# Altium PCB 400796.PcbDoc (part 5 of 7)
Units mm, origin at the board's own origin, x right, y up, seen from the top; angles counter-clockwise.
Board outline 53 x 53 mm, 6 copper layers (Top Layer, Mid Layer 1, Mid Layer 2, Mid Layer 3, Mid Layer 4, Bottom Layer), stack 1.494 mm thick; 319 components, 236 nets, 1249 pads, 2569 vias.
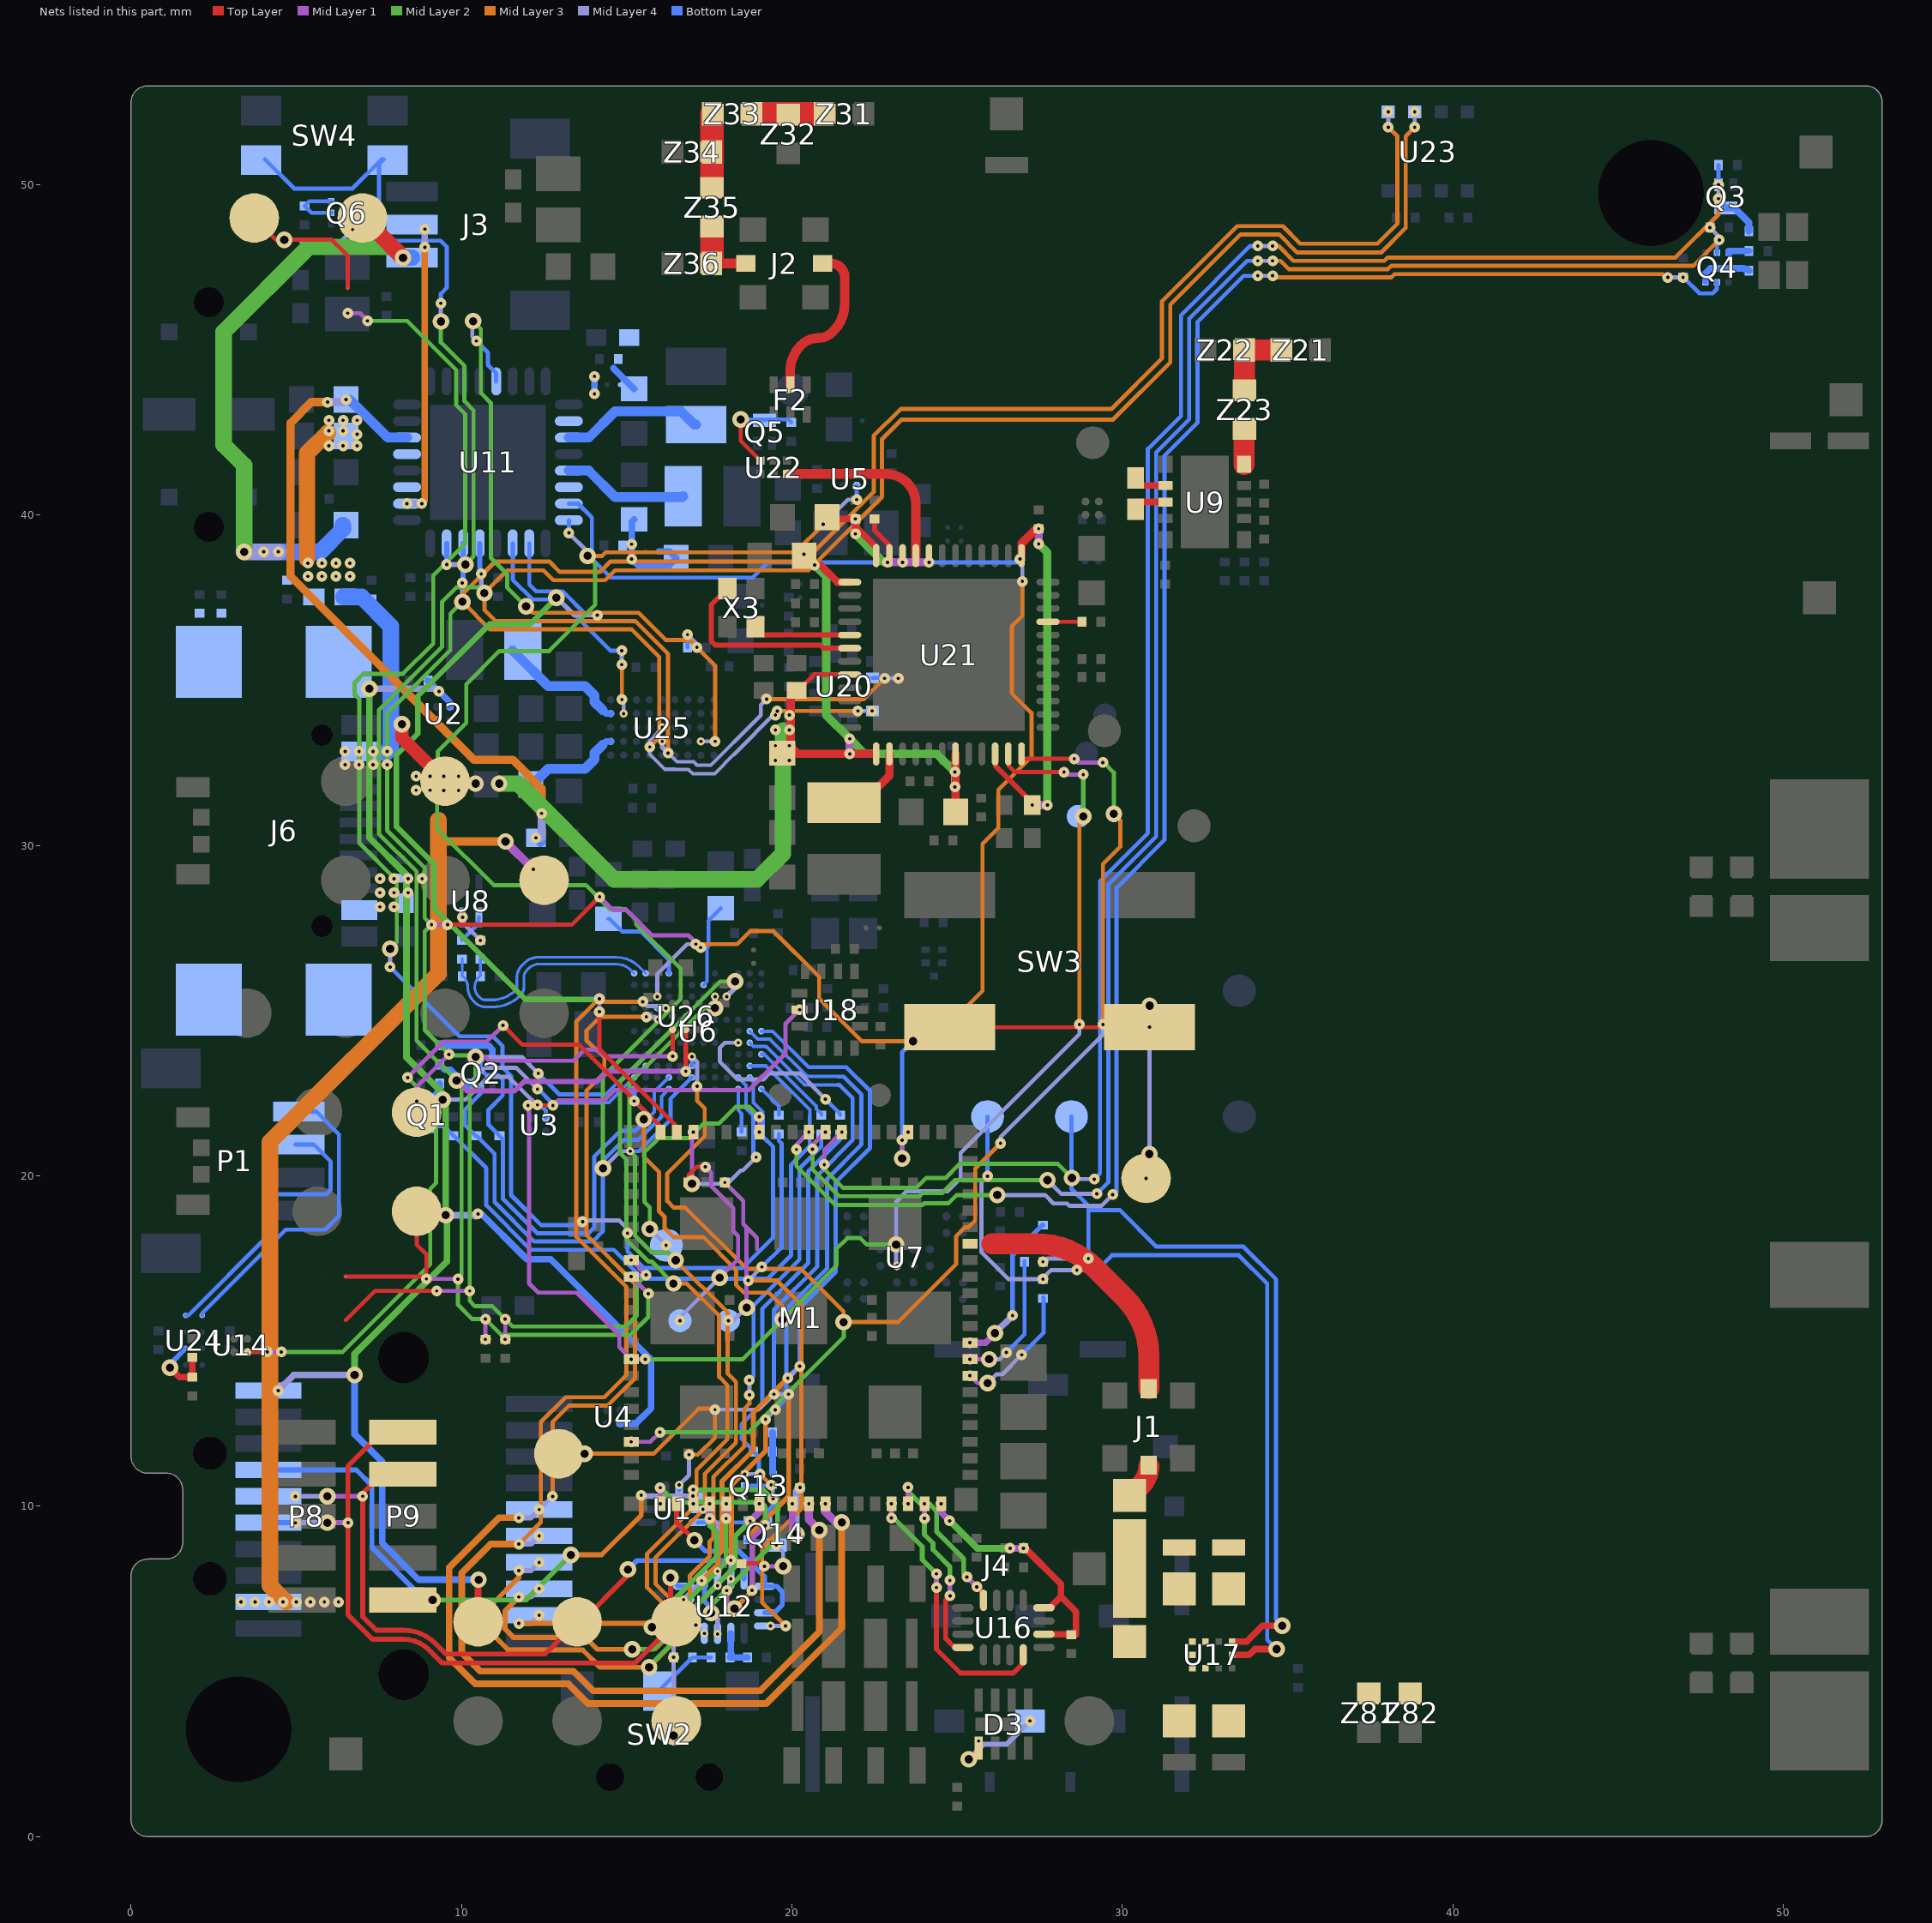
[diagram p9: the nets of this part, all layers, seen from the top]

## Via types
v1: diameter 0.325, hole 0.1, Mid Layer 4 to Bottom Layer, tented both sides, 675 vias
v2: diameter 0.325, hole 0.1, Top Layer to Mid Layer 1, tented both sides, 569 vias
v3: diameter 0.325, hole 0.1, Mid Layer 3 to Mid Layer 4, tented both sides, 384 vias
v4: diameter 0.5, hole 0.25, Mid Layer 1 to Mid Layer 4, tented both sides, 312 vias
v5: diameter 0.325, hole 0.1, Mid Layer 1 to Mid Layer 2, tented both sides, 265 vias
v6: diameter 0.5, hole 0.25, Top Layer to Bottom Layer, tented both sides, 175 vias
v7: diameter 0.25, hole 0.1, Mid Layer 4 to Bottom Layer, tented both sides, 105 vias
v8: diameter 0.325, hole 0.1, Top Layer to Mid Layer 1, tented top, 67 vias
v9: diameter 0.25, hole 0.1, Top Layer to Mid Layer 1, tented both sides, 17 vias

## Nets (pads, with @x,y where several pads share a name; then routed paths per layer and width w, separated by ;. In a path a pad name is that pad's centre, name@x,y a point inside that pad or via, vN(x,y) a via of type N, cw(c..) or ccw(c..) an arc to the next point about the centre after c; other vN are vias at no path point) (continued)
NetF2_6: F2.6 J2.1 | length 5
  Top Layer w0.29: F2.6@19.95,43.95 19.95,44.376 cw(c21.024,44.376) 20.265,45.136 20.275,45.146 cw(c20.8,44.622) 20.8,45.364 ccw(c20.8,45.959) 21.22,45.538 21.254,45.572 ccw(c20.421,46.406) 21.6,46.406 21.6,47.201 ccw(c21.173,47.201) 21.475,47.503 ccw(c21.183,47.211) 21.183,47.623 J2.1@20.928,47.623
NetJ1_1: J1.1 M1.35 | length 7.5
  Top Layer w0.638: 26.061,17.949 27.386,17.949 cw(c27.386,15.409) 29.182,17.205 30.056,16.331 cw(c28.26,14.535) 30.8,14.535 J1.1@30.8,13.56
NetJ1_3: J1.3 Z7.1 | length 1.1
  Top Layer w0.638: Z7.1@30.219,10.295 30.564,10.64 ccw(c29.994,11.21) J1.3@30.8,11.21
NetJ2_3: J2.3 Z35.1 Z36.1 | length 2.1
  Top Layer w0.29: Z36.1@17.582,47.623 J2.3@18.608,47.623
  Top Layer w0.71: Z36.1@17.582,47.623 Z35.1@17.581,48.719
NetL1_2: L1.2 U6.B6 | length 2.5
  Bottom Layer w0.105: U6.B6@17.325,25.78 17.432,25.887 17.432,26.907 17.475,26.95
  Bottom Layer w0.125: 17.475,26.95 17.475,27.73 L1.2@17.85,28.105
NetL2_2: L2.2 U6.A9 | length 2.8
  Bottom Layer w0.125: L2.2@14.45,27.78 14.475,27.78 14.854,27.401 15.423,27.401 16.275,26.549 U6.A9@16.275,26.13
NetL5_1: L5.1 U9.8 | length 1
  Top Layer w0.2: L5.1@30.4,40.25 30.55,40.4 30.667,40.4 U9.8@31.313,40.4
NetL5_2: L5.2 U9.7 | length 1
  Top Layer w0.2: L5.2@30.4,41.05 30.55,40.9 30.667,40.9 U9.7@31.313,40.9
NetL6_1: L6.1 U21.26 | length 2.4
  Top Layer w0.254: L6.1@21.575,31.297 22.063,31.785 22.621,31.785 22.95,32.113 U21.26@22.95,32.775
NetM1_2: M1.2 SB6.1 | length 6.6
  Mid Layer 1 w0.15: v2(16.013,10.075) v5(16.013,10.56) ; v2(18.793,7.452) 18.793,9.017 v5(19.192,9.415)
  Mid Layer 2 w0.15: v5(16.013,10.56) 16.452,10.121 19.064,10.121 19.192,9.993 v5(19.192,9.415)
NetM1_3: M1.3 U12.5 U12.7 | length 5.8
  Top Layer w0.15: M1.3@16.513,10.075 16.513,9.509 v6(17.051,8.97)
  Bottom Layer w0.15: v6(17.051,8.97) 17.381,8.64 18.397,8.64 19.175,7.863 U12.5@19.175,7.575 19.543,7.575 19.71,7.409 19.71,7.009 19.475,6.775 U12.7@19.175,6.775
NetM1_4: M1.4 U12.1 U12.11 | length 9.8
  Mid Layer 1 w0.15: v2(17.013,10.075) v5(17.013,10.498)
  Mid Layer 2 w0.15: v5(17.013,10.498) 19.127,10.498 19.564,10.06 19.564,9.008 17.555,6.998 v4(17.555,6.767)
  Mid Layer 4 w0.15: v4(17.555,6.767) 17.75,6.571 v7(17.75,6.132)
  Bottom Layer w0.15: U12.1@17.35,7.8 17.35,7.124 17.75,6.724 U12.11@17.75,6.15 v7(17.75,6.132)
NetM1_10: M1.10 R1.2 | length 2.7
  Mid Layer 1 w0.203: v2(20.017,10.075) 20.017,9.266 v4(20.133,9.15) ; v4@20.057,9.074 v4@20.133,8.998
  Mid Layer 4 w0.203: v4@20.133,8.998 v4(20.133,9.15) 20.133,10.456 v1(20.242,10.566)
NetM1_27: M1.27 R27.1 | length 4.2
  Mid Layer 1 w0.125: v2(25.388,13.95) 25.61,13.728 v4(25.925,13.728)
  Mid Layer 4 w0.125: v4@26.077,13.728 v4(25.925,13.728) 26.189,13.992 26.362,13.992 v1(26.953,14.583)
  Bottom Layer w0.125: v1(26.953,14.583) 27.615,15.245 27.615,16.315 R27.1@27.6,16.315
NetM1_28: M1.28 R28.1 | length 4.2
  Mid Layer 1 w0.125: v2(25.388,14.45) v4(25.969,14.45)
  Mid Layer 4 w0.125: v4(25.969,14.45) 26.289,14.45 v1(26.489,14.651)
  Bottom Layer w0.125: v1(26.489,14.651) 27.04,15.201 R28.1@27.04,17.425
NetM1_29: M1.29 R29.1 | length 4.8
  Mid Layer 1 w0.2: v2(25.388,14.95) 25.856,14.95 v4(26.146,15.24)
  Mid Layer 4 w0.2: v4(26.146,15.24) 26.675,15.769 v1(26.675,15.773)
  Bottom Layer w0.15: v1(26.675,15.773) 26.675,17.603 27.582,18.51 R29.1@27.6,18.51
NetM1_44: M1.44 SW3.2 TP36.1 U6.C10 U11.7 | length 59.7
  Top Layer w0.125: SW3.2@24.775,24.5 v2(30.825,24.5)
  Mid Layer 1 w0.125: v4(23.335,20.526) 23.335,21.147 v2(23.513,21.325) ; v2(30.719,19.925) 30.82,20.026 v4(30.82,20.662) ; v2(30.825,24.5) v4(30.825,25.153)
  Mid Layer 3 w0.125: v3(17.089,27.015) 18.343,27.015 18.735,27.407 19.442,27.407 20.823,26.027 20.823,25.369 22.117,24.075 v6(23.663,24.075) 23.913,24.075 24.282,24.444 24.616,24.444 25.767,25.595 25.767,30.047 26.25,30.53 26.25,31.688 27.251,32.689 27.251,34.014 26.657,34.608 26.657,36.638 26.975,36.957 v3(26.975,38)
  Mid Layer 4 w0.125: v7(15.925,25.43) 15.925,26.111 16.829,27.015 v3(17.089,27.015) ; v4(23.335,20.526) v1(23.335,21.08) ; v1(26.9,38.675) 26.975,38.6 v3(26.975,38) ; v4(30.82,20.662) 30.825,20.667 v4(30.825,25.153)
  Bottom Layer w0.125: U11.7@13.25,40.35 13.525,40.35 13.875,40 13.947,39.928 13.947,38.685 14.52,38.112 18.812,38.112 19.275,38.575 26.8,38.575 v1(26.9,38.675) ; v1@23.391,21.055 23.335,21.11 23.335,23.746 v6(23.663,24.075)
NetM1_48: M1.48 Q3.1 R44.2 | length 56.9
  Mid Layer 1 w0.125: v5(20.979,20.343) 20.979,20.791 v2(21.513,21.325)
  Mid Layer 2 w0.125: v5(20.979,20.343) 20.979,20.207 21.549,19.637 23.758,19.637 24.056,19.935 24.646,19.935 25.077,20.366 28.044,20.366 v4(28.475,19.935)
  Mid Layer 3 w0.125: v3(34.55,48.15) 34.73,48.15 35.18,47.7 37.932,47.7 38.032,47.8 46.744,47.8 48.044,49.099 v3(48.044,49.583)
  Mid Layer 4 w0.125: v4(28.475,19.935) 28.508,19.902 v1(29.15,19.902) ; v1(34.1,48.15) v3(34.55,48.15) ; v3(48.044,49.583) v1(48.044,50.004)
  Bottom Layer w0.125: v1(29.15,19.902) 29.325,20.077 29.325,28.925 30.775,30.375 30.775,42.007 31.775,43.007 31.775,46.057 33.868,48.15 v1(34.1,48.15) ; v1(48.044,50.004) R44.2@48.044,50.601
NetM1_49: M1.49 Q4.5 R46.2 | length 56.9
  Mid Layer 1 w0.125: v5(20.627,20.809) 20.627,20.939 v2(21.013,21.325)
  Mid Layer 2 w0.125: v5(20.627,20.809) 20.627,20.185 21.427,19.385 23.859,19.385 23.958,19.484 24.555,19.484 24.943,19.871 v4(27.734,19.871)
  Mid Layer 3 w0.125: v3(34.55,47.7) 34.788,47.7 35.038,47.45 38.036,47.45 38.136,47.55 47.283,47.55 v3(48.068,48.334)
  Mid Layer 4 w0.125: v4(27.734,19.871) 28.153,19.452 29.225,19.452 v1(29.23,19.457) ; v1(34.1,47.7) v3(34.55,47.7) ; v1(47.786,48.708) 48.068,48.427 v3(48.068,48.334)
  Bottom Layer w0.125: v1(29.23,19.457) 29.575,19.802 29.575,28.821 31.025,30.271 31.025,41.904 32.025,42.904 32.025,45.954 33.771,47.7 v1(34.1,47.7) ; v1(47.786,48.708) 48,48.495 Q4.5@48,47.925
NetM1_50: M1.50 Q4.2 R45.2 | length 56
  Mid Layer 1 w0.125: v5(20.135,20.8) 20.135,20.947 v2(20.513,21.325)
  Mid Layer 2 w0.125: v5(20.135,20.8) 20.135,20.295 21.312,19.118 23.946,19.118 24.001,19.173 24.743,19.173 24.99,19.42 v4(26.218,19.42)
  Mid Layer 3 w0.125: v3(34.551,47.249) 34.6,47.2 38.139,47.2 38.239,47.3 46.356,47.3 46.456,47.2 v3(46.51,47.2)
  Mid Layer 4 w0.125: v4(26.218,19.42) 27.663,19.42 27.917,19.166 28.329,19.166 28.405,19.091 29.368,19.091 v1(29.711,19.434) ; v1(34.101,47.249) v3(34.551,47.249) ; v3(46.51,47.2) v1(46.975,47.2)
  Bottom Layer w0.125: v1(29.711,19.434) 29.734,19.434 29.825,19.525 29.825,28.718 31.275,30.168 31.275,41.8 32.275,42.8 32.275,45.85 33.674,47.249 v1(34.101,47.249) ; R45.2@46.975,47.21 47.472,46.712 47.865,46.712 47.992,46.84 47.992,47.067 Q4.2@48,47.075
NetM1_53: M1.53 TP23.1 | length 7.6
  Mid Layer 1 w0.125: v2(19.013,21.325) v5(19.013,21.79)
  Mid Layer 2 w0.125: v4(15.7,18.39) 15.7,19.052 15.534,19.218 15.534,20.707 15.971,21.144 16.893,21.144 17.337,21.587 17.796,21.587 18.296,22.087 18.716,22.087 v5(19.013,21.79)
  Mid Layer 4 w0.125: v4@15.777,18.314 v1(16.19,17.9)
  Bottom Layer w0.125: v1(16.19,17.9) TP23.1@16.2,17.9
NetM1_59: M1.59 U14.B2 | length 22.5
  Top Layer w0.127: U14.B2@3.519,14.664 4.118,14.664 v2(4.124,14.67) ; v2(11.256,24.556) 11.836,23.976 13.552,23.976 14.148,23.379 16.013,21.514 M1.59@16.013,21.325
  Mid Layer 1 w0.127: v2(4.124,14.67) v5(4.549,14.67) ; v5(8.369,22.975) 9.462,24.069 10.769,24.069 v2(11.256,24.556)
  Mid Layer 2 w0.127: v5(4.549,14.67) 6.405,14.67 9.054,17.319 9.054,19.601 9.226,19.773 9.226,21.823 8.836,22.213 8.836,22.508 v5(8.369,22.975)
NetM1_99: M1.99 TP39.1 | length 5.6
  Mid Layer 1 w0.125: v2(17.967,19.8) 18.525,19.242 18.525,18.539 18.628,18.436 ; v4(18.628,16.013) 18.628,18.436 ; 18.941,17.786 18.941,18.124 18.628,18.436
  Mid Layer 4 w0.125: v1(18.077,15.617) 18.232,15.617 v4(18.628,16.013)
NetM1_101: M1.101 TP40.1 | length 6.6
  Top Layer w0.125: M1.101@16.867,19.8 16.867,20.021 17.117,20.271 v2(17.381,20.271)
  Mid Layer 1 w0.125: v2(17.381,20.271) 17.552,20.1 17.552,19.699 18.229,19.022 18.229,18.32 18.371,18.178 18.371,17.478 v4(17.81,16.917)
  Mid Layer 4 w0.125: v1(16.61,15.616) 16.61,15.717 v4(17.81,16.917)
NetP1_3: P1.3 U24.A2 | length 8.8
  Bottom Layer w0.125: U24.A2@1.65,15.775 1.729,15.775 4.112,18.158 4.112,19.328 4.229,19.445 5.91,19.445 6.04,19.575 6.04,20.435 5.525,20.95 P1.3@5.075,20.95 P1.3@4.975,20.95
NetP1_4: P1.4 U24.A1 | length 9.1
  Bottom Layer w0.125: U24.A1@2.15,15.775 2.15,15.842 4.683,18.375 5.875,18.375 6.29,18.79 6.29,20.823 6.288,20.825 6.288,21.259 5.596,21.95 P1.4@5.325,21.95
NetP9_10: P9.10 R3.1 TP1.1 U2.B2 U3.B2 U4.B2 | length 53.5
  Top Layer w0.2: TP1.1@10.5,6.5 10.5,7.759 v6(10.516,7.774)
  Mid Layer 2 w0.2: v6(6.764,13.973) 6.764,14.614 9.557,17.407 9.557,18.775 v4(9.523,18.81) 9.523,22.189 9.403,22.308 9.403,22.521 8.335,23.59 8.335,29.112 7.212,30.234 v4(7.212,34.75)
  Mid Layer 4 w0.125: v4@9.403,22.308 v4@9.418,22.323 ; v4(9.433,22.308) 10.118,22.308 10.807,22.997 11.433,22.997 12.132,22.298 12.28,22.15 v1(12.3,22.15)
  Mid Layer 4 w0.2: v1(4.45,13.5) 4.923,13.973 v6(6.764,13.973) ; v4(7.212,34.75) 9.175,34.75 v1@9.275,34.65 ; v4(9.523,18.81) 10.388,18.81 10.424,18.774 v1(10.5,18.85)
  Bottom Layer w0.125: v1(12.3,22.15) 12.375,22.15 12.55,21.975 U3.B2@12.55,21.75
  Bottom Layer w0.2: v6(6.764,13.973) 6.764,12.18 7.6,11.345 7.6,8.883 8.709,7.774 v6(10.516,7.774) ; R3.1@8.985,35 v1(9.318,34.667) 9.65,34.335 U2.B2@9.65,34.2 ; v1(10.5,18.85) 10.6,18.85 11.862,17.588 11.975,17.475 12.7,17.475 15.738,14.437 15.738,12.963 15.275,12.5 U4.B2@14.8,12.5
NetQ1_1: Q1.1 R41.2 U6.J2 | length 20.7
  Bottom Layer w0.105: 19.213,23.33 20.539,22.004 20.539,21.819
  Bottom Layer w0.125: Q1.1@9.175,21.5 9.465,21.5 R41.2@9.75,21.215 ; R41.2@9.76,21.225 10.75,20.235 10.75,19.107 12.094,17.762 14.609,17.762 15.489,16.883 19.261,16.883 19.974,17.596 19.974,20.334 20.539,20.899 20.539,21.819 ; U6.J2@18.725,23.33 19.213,23.33
NetQ1_3: Q1.3 R20.1 | length 0.8
  Bottom Layer w0.2: Q1.3@8.95,22.2 9.335,22.585 R20.1@9.335,22.8
NetQ2_2: Q2.2 R38.2 U6.K9 | length 14.1
  Bottom Layer w0.105: 15.717,21.819 15.838,21.939 15.838,22.543 16.032,22.737 U6.K9@16.275,22.98
  Bottom Layer w0.125: Q2.2@10.586,23.534 10.586,23.209 10.736,23.059 11.101,23.059 11.249,22.912 11.249,22.434 10.812,21.998 10.812,21.627 10.81,21.625 10.81,21.552 ; 10.812,21.552 11.25,21.115 11.25,19.314 12.301,18.262 13.838,18.262 14.016,18.441 14.016,20.574 14.803,21.361 15.26,21.361 15.717,21.819
NetQ2_3: Q2.3 R21.1 | length 2
  Bottom Layer w0.2: R21.1@9.335,23.937 10.824,23.937 10.936,23.825 Q2.3@10.936,23.534 ; R21.1@9.335,23.95 R21.1@9.335,23.988
NetQ2_5: Q2.5 R42.2 U6.L9 | length 13.4
  Bottom Layer w0.105: 16.05,21.819 16.05,22.405 U6.L9@16.275,22.63
  Bottom Layer w0.125: R42.2@10.439,21.204 10.1,21.543 10.1,22.008 10.586,22.494 Q2.5@10.586,22.684 ; R42.2@10.45,21.215 11,20.665 11,19.21 12.198,18.012 13.971,18.012 14.276,18.317 14.276,20.448 14.922,21.094 15.362,21.094 16.05,21.782 16.05,21.819
NetQ2_6: Q2.6 R19.1 | length 1.2
  Bottom Layer w0.2: R19.1@9.335,23.375 9.495,23.215 9.661,23.215 10.192,22.684 Q2.6@10.236,22.684
NetQ3_3: Q3.3 R12.1 | length 1.2
  Bottom Layer w0.2: Q3.3@48.269,49.304 48.525,49.304 48.965,48.863 R12.1@48.965,48.6 R12.1@48.965,48.633
NetQ4_3: Q4.3 R14.1 | length 1.8
  Bottom Layer w0.2: Q4.3@47.65,47.075 47.65,47.318 47.807,47.475 48.193,47.475 ; 48.093,47.475 48.193,47.475 ; R14.1@48.965,47.4 48.965,47.415 48.93,47.45 48.838,47.45 48.813,47.475 48.193,47.475
NetQ4_6: Q4.6 R13.1 | length 0.7
  Bottom Layer w0.2: Q4.6@48.35,47.925 48.35,48 R13.1@48.965,48
NetQ5_3: Q5.3 R62.2 U22.6 | length 3.1
  Top Layer w0.125: v6(18.45,42.9) 18.45,42.25 U22.6@19.05,41.65
  Bottom Layer w0.125: v6(18.45,42.9) 19.15,42.9 Q5.3@19.175,42.875 ; Q5.3@19.175,42.9 19.885,42.9 R62.2@19.975,42.81
NetQ6_2: Q6.2 Q6.3 R64.1 | length 1.8
  Bottom Layer w0.125: Q6.2@6.079,49.155 5.464,49.155 R64.1@5.254,49.365 5.394,49.505 Q6.3@6.079,49.505
NetQ6_6: Q6.6 SB7.2 TP35.1 | length 6.9
  Top Layer w0.125: TP35.1@3.726,49 4.386,48.34 v6(4.636,48.34) 6.076,48.34 6.555,47.861 SB7.2@6.555,46.88
  Mid Layer 4 w0.125: v6(4.636,48.34) 5.094,48.34 5.212,48.223 6.28,48.223 v7(6.705,48.648)
  Bottom Layer w0.125: v7(6.705,48.648) 6.862,48.805 Q6.6@6.929,48.805
NetQ13_2: Q13.2 Q13.5 R16.2 R107.1 R108.1 U1.5 | length 15.7
  Bottom Layer w0.125: U1.5@17.155,9.506 17.159,9.51 18.649,9.51 19,9.861 19,10.625 ; Q13.2@18.575,10.625 19,10.625 ; Q13.5@19.425,10.625 19,10.625 ; R16.2@21.462,21.27 21.462,21.103 20.493,20.133 20.493,17.36 19.103,15.97 19.103,13.105 18.478,12.481 18.478,12.037 18.843,11.672 R107.1@18.843,11.654 19,11.497 19,10.625
  Bottom Layer w0.15: Q13.5@19.425,10.625 Q13.5@19.449,10.649
NetQ13_3: Q13.3 Q13.6 Q14.1 | length 2.2
  Mid Layer 3 w0.125: v3(19.038,10.975) v3(19.37,10.643)
  Mid Layer 4 w0.125: v7(18.575,10.975) v3(19.038,10.975) ; v3(19.37,10.643) 19.425,10.588 v1(19.425,10.224)
  Bottom Layer w0.125: Q14.1@19.275,9.525 19.275,9.875 19.425,10.025 v1(19.425,10.224) Q13.6@19.425,10.275
NetQ13_4: Q13.4 R106.2 R107.2 | length 1.3
  Bottom Layer w0.203: R106.2@19.413,12.235 R107.2@19.413,11.654 19.413,10.987 Q13.4@19.425,10.975
NetQ14_3: Q14.3 R2.1 R108.2 | length 3
  Top Layer w0.125: R2.1@18.48,8.268 19.082,8.268 v2(19.167,8.183)
  Mid Layer 1 w0.125: v2(19.167,8.183) v4@19.704,8.183 ; v4@19.704,8.158 v4(19.734,8.188)
  Mid Layer 4 w0.125: v1(19.526,8.825) 19.734,8.616 v4(19.734,8.188)
  Bottom Layer w0.125: R108.2@18.629,8.94 19.411,8.94 v1(19.526,8.825)
NetR4_2: R4.2 U12.8 | length 17.8
  Mid Layer 3 w0.125: v3(18.679,16.834) 19.546,16.834 20.287,16.093 20.287,9.929 19.096,8.739 19.096,7.087 v3(19.808,6.375)
  Mid Layer 4 w0.125: v3(18.679,16.834) v1(19.089,17.244) ; v7(19.353,6.375) v3(19.808,6.375)
  Bottom Layer w0.125: v1(19.089,17.244) 19.691,17.846 19.691,20.978 19.605,21.065 R4.2@19.605,21.27
NetR5_2: R5.2 R15.1 U24.C2 | length 2.2
  Top Layer w0.152: v6@1.167,14.202 v6(1.175,14.195)
  Top Layer w0.203: v6(1.175,14.195) 1.461,13.908 R15.1@1.852,13.908 1.854,13.909 R5.2@1.854,14.502
  Bottom Layer w0.152: v6(1.175,14.195) 1.175,14.3 U24.C2@1.65,14.775
NetR6_2: R6.2 U12.12 | length 16.9
  Mid Layer 3 w0.125: v3(17.096,6.404) 16.912,6.589 16.912,7.896 17.511,8.494 17.511,8.931 17.623,9.043 17.623,10.88 18.561,11.818 18.561,12.947 18.714,13.1 v3(18.714,13.366)
  Mid Layer 4 w0.125: v3(17.096,6.404) v7(17.35,6.15) ; v3(18.714,13.366) v1(18.714,13.815)
  Bottom Layer w0.125: v1(18.714,13.815) 18.841,13.942 18.841,16.079 20.227,17.466 20.227,20.222 20.891,20.885 R6.2@20.891,21.27
NetR11_2: R11.2 U6.L3 | length 1.3
  Bottom Layer w0.105: U6.L3@18.375,22.63 18.375,21.985 18.475,21.884 18.475,21.819
  Bottom Layer w0.125: R11.2@18.475,21.335 18.475,21.819
NetR17_1: R17.1 R32.2 U12.10 | length 1.3
  Bottom Layer w0.203: U12.10@18.15,6.15 18.15,5.447 R17.1@18.125,5.422 R32.2@18.657,5.422
NetR17_2: R17.2 R18.1 SW2.2 | length 2
  Bottom Layer w0.125: SW2.2@16,4.4 16,4.432 R18.1@16.99,5.422 R17.2@17.555,5.422
NetR18_2: R18.2 TP28.1 U1.4 U12.2 | length 7.2
  Mid Layer 4 w0.125: v6(16.418,3.053) v1(16.418,5.424) 16.418,6.265 v7(17.75,7.597) ; v7(17.308,9.906) 17.75,9.464 v7(17.75,8.029)
  Bottom Layer w0.125: v1(16.418,5.424) R18.2@16.42,5.422
NetR31_2: R31.2 U8.7 | length 0.9
  Mid Layer 4 w0.125: v1(10.032,27.828) ccw(c10.419,27.828) 10.145,27.554 v1(10.572,27.128)
NetR34_2: R34.2 U8.6 | length 0.8
  Bottom Layer w0.125: R34.2@10.02,27.153 10.022,27.153 10.28,27.41 ; 10.299,27.43 10.41,27.54 ccw(c10.127,27.823) U8.6@10.527,27.823
NetSB6_2: SB6.2 TP5.1 U1.2 U6.G2 | length 32.4
  Top Layer w0.125: TP5.1@12.946,11.588 v6(13.725,11.588)
  Top Layer w0.15: v2(18.031,7.444) 18.093,7.444 v2@18.093,7.452
  Mid Layer 1 w0.15: v2@18.032,7.443 v2(18.031,7.444) 18.031,7.131 v4(18.26,6.902)
  Mid Layer 3 w0.125: v6(13.725,11.588) 15.811,11.588 17.173,12.951 17.641,12.951 v3(17.67,12.921) 17.67,12.071 17.157,11.558 v3(16.886,11.558)
  Mid Layer 3 w0.15: v4(18.26,6.902) 18.81,7.452 18.81,9.212 19.901,10.303 v3(19.901,13.39)
  Mid Layer 4 w0.125: v7(16.586,10.642) 16.886,10.942 v3(16.886,11.558) ; v3(17.67,12.921) 18.987,12.921 v1(19.456,13.39)
  Mid Layer 4 w0.15: v1(19.456,13.39) v3(19.901,13.39)
  Bottom Layer w0.105: U6.G2@18.725,24.03 18.832,23.923 19.202,23.923 19.214,23.911 19.232,23.911 20.393,22.75 21.387,22.75
  Bottom Layer w0.125: v6@13.716,11.579 v6(13.725,11.588) ; U1.2@16.586,10.475 v7(16.586,10.642) ; v1(19.456,13.39) 19.456,15.948 20.767,17.259 20.767,20.011 21.838,21.082 21.838,22.361 21.448,22.75 21.387,22.75
NetSB7_1: SB7.1 U6.K2 | length 48.8
  Mid Layer 1 w0.125: v2(6.556,46.118) 6.922,46.118 v5(7.155,45.885)
  Mid Layer 2 w0.125: v5(7.155,45.885) 8.355,45.885 9.836,44.404 9.836,43.336 10.108,43.064 10.108,39.137 9.147,38.176 9.147,36.118 8.229,35.2 7.032,35.2 6.763,34.931 6.763,34.575 6.908,34.431 6.908,30.072 8.043,28.937 8.043,27.078 v4(7.839,26.874)
  Mid Layer 4 w0.125: v1(7.839,26.323) v4(7.839,26.874) ; v1(13.666,18.613) 13.703,18.65 14.777,18.65 15.022,18.405 v1(15.022,18.266)
  Bottom Layer w0.105: U6.K2@18.725,22.98 18.832,22.873 18.832,22.217 19.118,21.932 19.118,21.819
  Bottom Layer w0.125: v1(7.839,26.323) 9.937,24.226 10.949,24.226 11.243,23.932 11.243,23.278 11.5,23.021 11.5,19.417 12.405,18.512 13.565,18.512 v1(13.666,18.613) ; v1(15.022,18.266) 15.022,17.717 15.53,17.21 18.499,17.21 19.433,18.144 19.433,20.872 19.118,21.188 19.118,21.819
NetU6_F1: U6.F1 U12.15 | length 21.8
  Mid Layer 3 w0.15: v3(17.269,7.745) 17.774,8.249 17.774,8.532 17.888,8.646 17.888,10.754 18.832,11.698 18.832,12.834 v3(19.878,13.88)
  Mid Layer 4 w0.15: v7(16.725,7.175) 17.269,7.719 v3(17.269,7.745) ; v3(19.878,13.88) v1(20.234,14.237)
  Bottom Layer w0.105: U6.F1@19.075,24.38 19.077,24.377 19.417,24.377 20.503,23.291 21.387,23.291
  Bottom Layer w0.125: v1(20.234,14.237) 20.234,16.002 21.327,17.095 21.327,19.809 22.361,20.843 22.361,22.572 21.643,23.291 21.387,23.291
NetU6_F2: U6.F2 U12.3 | length 20.5
  Mid Layer 3 w0.15: v3(18.15,8.361) 18.169,8.38 18.169,10.636 19.202,11.669 v3(19.202,12.627)
  Mid Layer 4 w0.125: v3(19.202,12.627) v1(19.495,12.92)
  Mid Layer 4 w0.15: v7(18.15,7.8) v3(18.15,8.361)
  Bottom Layer w0.105: U6.F2@18.725,24.38 18.967,24.138 19.331,24.138 20.461,23.008 21.387,23.008
  Bottom Layer w0.125: v1(19.495,12.92) 19.83,13.255 19.83,15.964 21.067,17.202 21.067,19.911 22.101,20.944 22.101,22.475 21.568,23.008 21.387,23.008
NetU9_5: U9.5 Z23.1 | length 1.1
  Top Layer w0.638: U9.5@33.688,41.543 33.688,42.577 Z23.1@33.7,42.59
NetU12_13: U12.13
NetU21_9: U21.9 U22.3 | length 6
  Top Layer w0.29: U22.3@19.875,41.25 22.85,41.25 cw(c22.85,40.35) 23.75,40.35 U21.9@23.75,38.775
NetU21_17: U21.17 X3.1 | length 3
  Top Layer w0.152: X3.1@18.795,36.475 18.895,36.375 U21.17@21.75,36.375
NetU21_18: U21.18 X3.3 | length 6.1
  Top Layer w0.152: X3.3@18.045,37.775 18.045,37.725 17.846,37.526 17.796,37.526 17.563,37.293 17.563,36.184 17.675,36.071 17.678,36.071 17.679,36.07 20.852,36.07 20.947,35.975 U21.18@21.75,35.975
NetZ1_2: Z1.2 Z2.2 Z81.1 Z82.1
NetZ5_1: Z5.1 Z6.1 Z7.2 | length 2.2
  Top Layer w0.638: Z5.1@30.21,7.04 30.21,8.112 Z7.2@30.21,9.22
NetZ21_1: Z21.1 Z22.1 Z23.2 | length 2.3
  Top Layer w0.638: Z23.2@33.7,43.81 33.7,44.99 Z22.1@33.71,45 Z21.1@34.79,45
NetZ31_1: Z31.1 Z32.2 Z33.2 | length 3.3
  Top Layer w0.71: Z32.2@19.95,52.15 Z32.2@19.894,52.15 ; Z31.1@20.965,52.15 Z32.2@19.894,52.15 ; Z32.2@19.894,52.15 Z33.2@18.801,52.15 Z32.2@19.894,52.15
NetZ33_1: Z33.1 Z34.1 Z35.2 | length 2.2
  Top Layer w0.71: Z35.2@17.581,49.939 Z34.1@17.581,51.001 Z33.1@17.581,52.15
nPM60_ENABLE: R9.2 U11.29 U25.B2 | length 21.5
  Mid Layer 2 w0.125: v4(10.35,45.875) 10.587,45.638 10.587,43.698 10.89,43.396 10.89,38.709 11.235,38.364 11.381,38.218 11.381,37.813 v4(11.953,37.241)
  Mid Layer 3 w0.125: v4(11.953,37.241) 12.149,37.045 15.362,37.045 16.182,36.225 16.9,36.225 v3(17.125,36) 17.676,35.449 v3(17.676,33.155)
  Mid Layer 4 w0.125: v4@10.325,45.825 10.325,45.4 v1(10.45,45.275) ; v1(16.84,36.385) 17.125,36.1 v3(17.125,36) ; v7(17.245,33.155) v3(17.676,33.155)
  Bottom Layer w0.125: v1(10.45,45.275) 10.8,44.925 10.8,44.552 11.05,44.302 U11.29@11.05,44.05 ; R9.2@16.84,36 v1(16.84,36.385)
nPM60_READY: U11.11 U25.H4 | length 7.2
  Mid Layer 3 w0.125: v3(14.85,35.475) 14.855,35.47 v3(14.855,34.42)
  Mid Layer 4 w0.125: v3(14.85,35.475) v1(14.85,35.9) ; v7(14.905,33.995) v3@14.905,34.42
  Bottom Layer w0.125: U11.11@11.55,39.15 11.55,38.05 12.152,37.448 12.955,37.448 14.502,35.9 v1(14.85,35.9)
nPM1300_INT: M1.58 U11.10 | length 28.9
  Top Layer w0.125: v2(14.173,24.97) 14.173,23.834 16.513,21.494 M1.58@16.513,21.325
  Mid Layer 1 w0.125: v2(14.173,24.97) v5(14.173,25.361)
  Mid Layer 2 w0.17: v4(12.872,37.498) 12.077,36.703 10.848,36.703 8.675,34.53 8.675,33.385 8.03,32.74 8.03,30.577 9.169,29.438 9.169,28.108 11.932,25.344 14.156,25.344 v5(14.173,25.361)
  Mid Layer 4 w0.125: v4(12.872,37.498) 13.396,36.975 v1(14.11,36.975)
  Bottom Layer w0.125: U11.10@12.05,39.15 12.05,37.904 12.256,37.698 13.058,37.698 13.781,36.975 v1(14.11,36.975)
NTC: J3.2 U11.18 | length 8.8
  Mid Layer 3 w0.2: v3(8.8,40.35) 8.887,40.438 v3(8.887,48.112)
  Mid Layer 4 w0.2: v1(8.35,40.35) v3(8.8,40.35) ; v3(8.887,48.112) v1(8.887,48.662)
P0.08/TRACEDATA3: M1.12 P9.15 U6.E10 | length 43.5
  Mid Layer 1 w0.25: v2(21.013,10.075) 21.013,9.826 21.328,9.511 v4(21.508,9.511)
  Mid Layer 3 w0.125: v3(12.757,10.296) 12.757,12.55 13.255,13.048 14.428,13.048 15.25,13.87 15.25,16.734 13.786,18.199 13.786,22.591 14.322,23.127 14.322,23.584 14.047,23.859 14.02,23.859 13.786,24.094 13.786,24.408 14.193,24.815 v3(15.595,24.815)
  Mid Layer 3 w0.203: v3(11.738,9.65) 11.137,9.65 9.625,8.138 9.625,5.417 10.418,4.623 13.228,4.623 13.823,4.028 19.219,4.028 21.508,6.317 v4(21.508,9.511)
  Mid Layer 4 w0.125: v1(12.35,9.899) 12.36,9.899 v3(12.757,10.296) ; v3@15.57,24.815 v3@15.582,24.802 ; v3(15.595,24.815) 15.865,24.815 v7(15.95,24.73)
  Mid Layer 4 w0.152: v3(11.738,9.65) 12.101,9.65 v1(12.35,9.899)
P0.09/TRACEDATA2: M1.11 P9.16 U6.D10 | length 43.1
  Mid Layer 1 w0.25: v2(20.513,10.075) 20.513,9.596 v4(20.83,9.279)
  Mid Layer 3 w0.125: v3(11.738,8.851) 12.403,9.515 12.403,12.552 13.149,13.299 14.323,13.299 14.994,13.97 14.994,16.635 13.469,18.16 13.469,24.669 14.07,25.271 v3(15.485,25.271)
  Mid Layer 3 w0.203: v3(11.738,8.851) 10.88,8.851 10.007,7.979 10.007,5.566 10.566,5.008 13.388,5.008 13.988,4.408 19.036,4.408 20.83,6.202 v4(20.83,9.279)
  Mid Layer 4 w0.125: v3(15.485,25.271) 15.616,25.139 16.123,25.139 v7(16.185,25.077)
  Mid Layer 4 w0.152: v3(11.738,8.851) 12.101,8.851 v1(12.35,9.1)
  Bottom Layer w0.125: U6.D10@15.925,25.08 v7@16.182,25.08
  Bottom Layer w0.25: v7@16.182,25.08 v7(16.185,25.077)
P0.10/TRACEDATA1: M1.8 P9.17 U6.C5 | length 39.4
  Mid Layer 1 w0.203: v5(18.734,9.548) 19.013,9.827 v2(19.013,10.075)
  Mid Layer 2 w0.125: v4(16.482,17.443) 16.248,17.678 15.766,17.678 15.247,18.197 15.247,20.606 15.079,20.774 15.079,21.819 15.079,22.804 17.354,25.078 v4(17.675,25.078)
  Mid Layer 2 w0.152: v4(15.679,5.121) 15.679,5.153 16.533,6.007 16.533,6.421 18.294,8.182 18.294,9.108 v5(18.734,9.548)
  Mid Layer 3 w0.125: v4(15.679,5.121) 16.634,6.077 16.634,6.887 15.871,7.651 15.871,8.446 17.367,9.942 17.367,10.986 18.306,11.925 18.306,13.768 18.05,14.024 18.05,15.876 v4(16.482,17.443)
  Mid Layer 3 w0.152: v3(11.738,8.051) 11.738,7.847 10.94,7.05 10.94,6.122 11.413,5.65 13.666,5.65 14.195,5.121 v4(15.679,5.121)
  Mid Layer 4 w0.152: v3(11.738,8.051) 12.101,8.051 v1(12.35,8.3) ; v4(17.675,25.078) v7(17.675,25.43)
P0.11/TRACEDATA0: M1.6 P9.18 U6.C4 | length 38.3
  Mid Layer 1 w0.203: v5(18.008,9.625) v2@18.008,10.075
  Mid Layer 2 w0.125: v4(16.416,16.742) 16.106,17.052 16.106,17.057 15.757,17.407 15.66,17.407 14.988,18.078 14.988,20.499 14.796,20.69 14.796,21.819 14.796,22.856 17.826,25.886 v4(18.279,25.886)
  Mid Layer 2 w0.152: v4(15.168,5.668) 15.797,5.668 16.251,6.122 16.251,6.554 18.008,8.311 v5(18.008,9.625)
  Mid Layer 3 w0.125: v4(15.168,5.668) 15.865,5.668 16.376,6.179 16.376,6.781 15.61,7.546 15.61,8.554 17.111,10.055 17.111,11.093 18.049,12.031 18.049,13.663 17.795,13.917 17.795,15.766 16.819,16.742 v4(16.416,16.742)
  Mid Layer 3 w0.152: v3(11.738,7.251) 11.322,6.835 11.322,6.276 11.569,6.029 13.749,6.029 14.11,5.668 v4(15.168,5.668)
  Mid Layer 4 w0.152: v3(11.738,7.251) 12.101,7.251 v1(12.35,7.5) ; v7(18.025,25.43) 18.279,25.684 v4(18.279,25.886)
  other v2: 18.013,10.075
P0.12/TRACECLK: M1.5 P9.19 | length 9.4
  Mid Layer 1 w0.203: v5(17.513,9.625) v2(17.513,10.075)
  Mid Layer 2 w0.152: v4(15.762,6.336) 15.762,6.5 17.717,8.455 17.717,9.211 17.513,9.415 v5(17.513,9.625)
  Mid Layer 3 w0.152: v3(11.738,6.451) 15.647,6.451 v4(15.762,6.336)
  Mid Layer 4 w0.152: v3(11.738,6.451) 12.101,6.451 v1(12.35,6.7)
PALDO: C62.1 C63.2 U21.8 U21.10 U21.12 | length 5.3
  Top Layer w0.2: C63.2@21.086,40.125 21.321,39.89 v2(21.925,39.89) 21.925,39.654 22.55,39.029 U21.12@22.55,38.775
  Mid Layer 1 w0.25: v5(21.925,39.433) v2(21.925,39.89) ; v5(22.893,38.575) v2(23.35,38.575) v2(24.15,38.575)
  Mid Layer 2 w0.25: v5(21.925,39.433) 22.783,38.575 v5(22.893,38.575)
PVSS1: C9.1 C47.1 C52.1 NT1.2 U11.2 | length 1.4
  Bottom Layer w0.2: v1(14.025,43.675) v1(14.025,44.2) ; 14.6,44.45 C47.1@15.225,43.825
PVSS2: C48.1 C53.1 C74.1 NT2.2 U11.6 | length 3.4
  Bottom Layer w0.2: C48.1@15.225,39.875 15.15,39.8 v1(15.15,39.125) v1(15.15,38.675) 15.35,38.475 16.275,38.475 C53.1@16.5,38.7 16.3,38.9 NT2.2@15.975,38.9
PWRIOVDD: C41.2 C42.2 U21.1 U21.34 | length 12.2
  Top Layer w0.152: U21.34@26.15,32.775 26.159,32.766 26.159,32.414 27.312,31.262 27.348,31.225 v2(27.275,31.225)
  Top Layer w0.254: U21.1@26.95,38.775 26.95,39.147 27.393,39.59 v2(27.468,39.59) 27.483,39.59 27.491,39.582 C41.2@27.491,39.567 ; C41.2@27.445,39.567 27.445,39.582 C41.2@27.453,39.59
  Mid Layer 1 w0.25: v2(27.275,31.225) v5(27.732,31.225) ; v5(27.468,39.133) v2(27.468,39.59)
  Mid Layer 2 w0.25: v5(27.468,39.133) 27.732,38.869 v5(27.732,31.225)
QSPI_CLK: M1.73 TP38.1 U6.L12 U7.E3 U18.13 U21.35 | length 59.9
  Top Layer w0.125: v2(12.013,22.132) v2(12.764,22.132) ; U21.35@26.55,32.775 26.55,32.425 26.75,32.225 27.03,32.225 v2(28.235,32.225)
  Mid Layer 1 w0.125: v2(12.013,22.132) 12.013,21.974 12.041,21.946 12.041,16.743 12.321,16.464 13.485,16.464 14.775,15.174 14.775,14.813 v2(15.138,14.45) v5(15.56,14.45) ; v2(12.764,22.132) 12.921,22.289 14.337,22.289 14.649,22.6 ; v2(28.235,32.225) 28.311,32.149 v5(28.818,32.149)
  Mid Layer 1 w0.127: 14.649,22.6 18.703,22.6 19.805,23.702 19.805,24.603 v2(20.231,25.029)
  Mid Layer 2 w0.127: v5(15.56,14.45) 18.512,14.45 v4(19.714,15.652) 21.348,17.286 21.348,17.789 21.676,18.117 22.069,18.117 22.263,17.923 v4(23.155,17.923)
  Mid Layer 2 w0.15: v1(28.818,30.907) v5(28.818,32.149)
  Mid Layer 3 w0.125: v4(15.519,21.714) 15.519,20.577 15.975,20.121 15.975,18.937 16.146,18.766 16.146,18.419 16.417,18.147 17.315,18.147 18.311,17.151 18.311,16.699 18.547,16.463 19.307,16.463 19.714,16.056 v4(19.714,15.652) ; v3(28.701,24.584) 28.701,30.79 v1(28.818,30.907)
  Mid Layer 4 w0.125: v1(15.228,22.267) 15.519,21.975 v4(15.519,21.714) ; v7(23.175,17.275) 23.155,17.295 v4(23.155,17.923) 23.155,19.221 23.469,19.536 24.716,19.536 25.107,19.927 25.107,20.699 28.701,24.293 v3(28.701,24.584)
  Bottom Layer w0.15: v1@15.225,22.34 U6.L12@15.225,22.63
  other v3: 28.818,30.907
  other v4: 28.818,30.882
QSPI_SS: M1.78 U6.J7 U21.36 | length 44.7
  Top Layer w0.125: U21.36@26.95,32.625 v2(28.547,32.625)
  Mid Layer 1 w0.125: v2(15.138,11.95) 15.717,11.95 v5(16.006,12.239) ; v2(28.547,32.625) 28.659,32.512 v5(29.412,32.512)
  Mid Layer 2 w0.125: v5(29.412,32.512) 29.441,32.512 29.743,32.211 v4(29.743,30.961)
  Mid Layer 2 w0.127: v5(16.006,12.239) 18.689,12.239 21.566,15.116 v4(21.566,15.574)
  Mid Layer 3 w0.125: v3(17.13,22.712) 17.13,22.274 17.36,22.044 17.36,21.204 16.225,20.07 16.225,19.239 16.427,19.038 16.78,19.038 18.631,17.187 20.268,17.187 21.566,15.889 v4(21.566,15.574) 23.213,15.574 24.971,17.332 24.971,18.174 25.241,18.444 25.344,18.444 25.55,18.65 25.55,20.222 v3(26.315,20.988) ; v3(29.414,24.584) 29.414,29.444 29.937,29.967 29.937,30.767 v4(29.743,30.961)
  Mid Layer 4 w0.125: v7(16.975,23.609) 17.13,23.454 v3(17.13,22.712) ; v3(26.315,20.988) 26.315,21.174 29.414,24.272 v3(29.414,24.584)
  Bottom Layer w0.125: U6.J7@16.975,23.33 v7(16.975,23.609)
RESET: P8.10 P9.7 U1.3 | length 17.3
  Mid Layer 2 w0.15: v6(9.125,7.16) 11.947,7.16 v4(13.313,8.526)
  Mid Layer 3 w0.15: v4(13.313,8.526) 14.239,8.526 15.437,9.724 v3(15.437,10.329)
  Mid Layer 4 w0.15: v3(15.437,10.329) 15.46,10.306 v7(17.003,10.306)
  Bottom Layer w0.15: P9.7@4.15,11.1 6.817,11.1 7.289,10.628 7.289,8.758 8.574,7.473 8.812,7.473 v6(9.125,7.16)
RF1: U17.2 Z3.1
RF2: U17.8 Z1.1
RF3: U17.9 Z2.1
RF4: U17.1 Z4.1
RFC: U17.10 Z5.2
RFFE_BLE_WIFI_ENABLE: U5.B2 U6.K7 U11.8 | length 42.2
  Mid Layer 2 w0.125: v4(13.818,38.769) 14.043,38.544 14.043,37.278 12.652,35.887 11.146,35.887 10.142,34.883 10.142,33.714 9.284,32.856 9.284,32.109 9.264,32.089 9.264,30.511 10.974,28.801 13.759,28.801 14.488,28.072 14.965,28.072 15.286,27.752 15.286,27.618 16.632,26.271 16.632,25.351 14.281,23 v4(14.281,20.228)
  Mid Layer 3 w0.125: v4(13.818,38.769) 14.254,38.769 14.361,38.876 20.101,38.876 v3(20.95,39.725)
  Mid Layer 4 w0.125: v1(13.25,39.464) 13.818,38.897 v4(13.818,38.769) ; v4(14.281,20.228) 14.801,20.748 v7(15.106,20.748) ; v3(20.95,39.725) 21.699,40.474 v1(21.961,40.474)
  Bottom Layer w0.125: v1(13.25,39.464) U11.8@13.25,39.85 ; v7(15.106,20.748) 15.107,20.746 15.377,20.746 16.324,21.693 16.324,22.329 U6.K7@16.975,22.98 ; v1(21.961,40.474) U5.B2@21.961,40.899
RST: D3.1 J4.C2 | length 3
  Mid Layer 1 w0.15: v4(25.35,2.34) 25.65,2.64 v9(25.65,2.89)
  Mid Layer 4 w0.15: v4(25.35,2.34) 25.8,2.79 26.495,2.79 v1(27.205,3.5)
SCL: M1.67 R22.2 SB8.2 TP9.1 U6.J11 U11.14 U20.4 U23.4 U25.E3 U26.A3 | length 119.3
  Top Layer w0.125: SB8.2@6.494,15.635 7.374,16.515 v2(9.247,16.515) ; v2(9.575,27.605) 13.334,27.605 v2(14.178,28.449)
  Top Layer w0.127: v2(16.388,23.618) U26.A3@16.388,24.431
  Mid Layer 1 w0.125: v2(8.642,22.264) 8.642,22.697 v5(9.622,23.677) ; v5(9.094,27.605) v2(9.575,27.605) ; v2(9.247,16.515) v5(10.249,16.515) ; v2(11.323,15.05) v5(11.323,15.665) ; v2(15.138,17.45) v5(15.586,17.002)
  Mid Layer 1 w0.127: v4(10.425,23.6) 10.719,23.6 10.833,23.486 13.391,23.486 13.728,23.824 14.124,23.824 14.33,23.618 v2(16.388,23.618) ; v2(14.178,28.449) 14.578,28.049 14.993,28.049 15.757,27.284 16.866,27.284 v2(17.239,26.911)
  Mid Layer 2 w0.125: v5(9.622,23.677) 9.622,23.678 8.888,24.413 8.888,27.399 v5(9.094,27.605) 8.888,27.812 8.888,29.32 7.75,30.457 7.75,34 9.662,35.912 9.662,37.018 v4(10.025,37.38) ; v5@9.653,23.647 10.378,23.647 v4(10.425,23.6) 10.425,22.724 10.25,22.549 10.25,16.516 v5(10.249,16.515) 10.249,16.213 10.409,16.053 10.935,16.053 v5(11.323,15.665) 11.547,15.441 14.972,15.441 15.302,15.771 15.302,16.717 v5(15.586,17.002)
  Mid Layer 3 w0.125: v3(15.697,32.986) 15.984,33.274 15.984,35.716 15.155,36.545 10.86,36.545 v4(10.025,37.38) 10.025,37.603 11.02,38.598 12.66,38.598 12.973,38.285 14.192,38.285 14.505,38.598 20.369,38.598 22.475,40.704 22.475,42.401 23.29,43.216 29.669,43.216 31.199,44.746 31.199,46.474 33.225,48.5 33.475,48.75 34.86,48.75 35.39,48.219 37.716,48.219 38.325,48.829 38.325,51.471 v3(38.05,51.746) ; v3(19.557,34.073) 19.559,34.075 v3(21.997,34.075)
  Mid Layer 4 w0.105: 16.446,32.309 16.866,32.309 16.997,32.178 17.662,32.178 18.237,32.752
  Mid Layer 4 w0.107: v7(16.075,33.575) 15.779,33.256 15.701,33.172 15.697,33.168 v3(15.697,32.986) 15.697,32.775 16.163,32.309 16.446,32.309
  Mid Layer 4 w0.125: v4(10.425,23.6) 11.825,23.6 v1(12.325,23.1) ; 18.237,32.752 v3(19.557,34.073) ; v3(21.997,34.075) v1(22.427,34.075) ; v3(38.05,51.746) v1(38.05,52.211)
  Mid Layer 4 w0.15: v4@10.025,37.43 v1(10.025,37.95)
  Bottom Layer w0.105: 14.25,22.468 14.369,22.468 15.124,23.223 15.452,23.223 15.467,23.238 15.481,23.238 U6.J11@15.575,23.33 U6.J11@15.575,23.33
  Bottom Layer w0.125: v1(12.325,23.1) 12.957,22.468 14.25,22.468 ; v1(22.427,34.075) U20.4@22.435,34.075
  Bottom Layer w0.15: v1@10.05,38.05 U11.14@10.05,39.15
SCLK: R28.2 TP26.1 U17.6 | length 24.6
  Top Layer w0.2: U17.6@33.318,5.9 33.768,5.9 34.247,6.379 v6(34.84,6.379)
  Mid Layer 4 w0.125: 27.729,17.5 v1(28.973,17.5)
  Bottom Layer w0.125: TP26.1@28.46,21.795 28.46,19.611 28.975,19.096 28.975,18.964 ; v1(28.973,17.5) 28.975,17.5 28.975,18.964 ; v6(34.84,6.379) 34.654,6.565 34.654,16.869 33.663,17.86 31.029,17.86 29.924,18.964 28.975,18.964
  other v1: 27.6,17.4
SDA: M1.68 R23.2 SB9.2 TP10.1 U6.K12 U11.13 U20.2 U23.3 U25.E2 U26.A2 | length 113.2
  Top Layer w0.125: SB9.2@6.494,16.948 8.869,16.948 v2(8.938,16.879) 8.938,17.627 8.642,17.923 TP10.1@8.642,18.927
  Top Layer w0.152: v2(16.788,23.163) U26.A2@16.788,24.431
  Mid Layer 1 w0.125: v2(8.938,16.879) 9.887,16.879 v5(9.892,16.874) ; v2(10.723,15.05) v5(10.723,15.665) ; v2(15.138,16.95) v5(15.653,16.435)
  Mid Layer 1 w0.152: v4(9.852,22.885) 10.165,22.573 11.609,22.573 11.889,22.853 14.094,22.853 14.404,23.163 v2(16.788,23.163)
  Mid Layer 2 w0.125: v4(10.694,37.643) 10.519,37.818 9.844,37.818 9.412,37.386 9.412,36.016 7.5,34.104 7.5,30.354 8.638,29.216 8.638,24.1 v4(9.852,22.885) 10,22.737 10,16.982 v5(9.892,16.874) 9.892,16.096 10.322,15.665 v5(10.723,15.665) 11.205,15.183 15.106,15.183 15.653,15.731 v5(15.653,16.435)
  Mid Layer 3 w0.125: v3(16.252,32.801) 16.252,35.801 15.259,36.795 11.031,36.795 10.694,37.133 v4(10.694,37.643) 11.384,38.333 12.481,38.333 12.779,38.035 14.35,38.035 14.648,38.333 20.506,38.333 22.725,40.552 22.725,42.297 23.321,42.893 29.718,42.893 31.455,44.63 31.455,46.376 33.579,48.5 34.745,48.5 35.293,47.952 37.83,47.952 38.575,48.696 38.575,51.471 v3(38.85,51.746) ; v3(19.233,34.434) 22.178,34.434 v3(22.804,35.061)
  Mid Layer 4 w0.105: v3(16.252,32.801) 16.52,32.533 17.023,32.533 17.126,32.431 17.542,32.431 18.237,33.126
  Mid Layer 4 w0.125: v4(9.852,22.885) 10.329,22.885 10.719,23.275 11.65,23.275 v1(12.3,22.625) ; 18.237,33.126 19.061,33.95 19.061,34.262 v3(19.233,34.434) ; v3(22.804,35.061) v1(23.222,35.061) ; v3(38.85,51.746) v1(38.85,52.211)
  Mid Layer 4 w0.15: v1(10.6,38.225) 10.6,37.736 v4(10.694,37.643)
  Mid Layer 4 w0.152: v7(16.075,33.155) 16.075,32.978 v3(16.252,32.801)
  Bottom Layer w0.105: 14.25,22.218 14.462,22.218 U6.K12@15.225,22.98
  Bottom Layer w0.125: v1(12.3,22.625) 12.325,22.625 12.732,22.218 14.25,22.218 ; U20.2@22.435,35.075 23.208,35.075 v1(23.222,35.061)
  Bottom Layer w0.15: U11.13@10.55,39.15 10.55,38.275 v1(10.6,38.225)
SDATA: R27.2 TP34.1 U17.5 | length 26.4
  Top Layer w0.2: U17.5@33.318,5.5 33.843,5.5 34.018,5.675 v6(34.668,5.675)
  Mid Layer 4 w0.125: v1(25.92,19.992) 25.732,19.804 25.732,17.692 26.55,16.875 v1(27.6,16.875) ; v1@27.6,16.9 27.85,17.15 v1(28.625,17.15)
  Bottom Layer w0.125: v1(25.92,19.992) TP34.1@25.92,21.795 ; v1(28.625,17.15) 29.236,17.15 29.684,17.599 33.522,17.599 34.384,16.736 34.384,5.959 v6(34.668,5.675)
Shield: C101.2 C102.2 J6.SHLD
SHPHLD: Q6.5 SW4.1 U11.15 | length 20.9
  Mid Layer 2 w0.125: v4(9.375,45.864) 9.375,45.231 10.087,44.519 10.087,43.455 10.367,43.176 10.367,38.753 v4(10.12,38.506)
  Mid Layer 4 w0.125: v4@9.375,45.914 v1(9.375,46.415)
  Mid Layer 4 w0.15: v1(9.55,38.506) v4(10.12,38.506)
  Bottom Layer w0.125: SW4.1@4.05,50.775 4.938,49.887 6.695,49.887 7.583,50.775 7.65,50.775 7.5,50.625 7.5,49.148 ; Q6.5@6.929,49.155 7.493,49.155 7.5,49.148 ; v1(9.375,46.415) 9.375,46.707 9.55,46.882 9.55,48.125 9.363,48.312 7.625,48.312 7.5,48.437 7.5,49.148
  Bottom Layer w0.15: v1(9.55,38.506) U11.15@9.55,39.15
SIM.1V8: C34.2 M1.19 R49.2 U16.14 U16.16 | length 8.2
  Top Layer w0.2: v2(27.01,8.725) 27.06,8.725 28.144,7.641 28.144,7.268 ; U16.14@27.625,6.125 28.585,6.125 28.6,6.11 28.6,6.812 28.144,7.268 ; U16.16@27.625,6.925 27.801,6.925 28.144,7.268
  Mid Layer 1 w0.2: v2(24.513,10.075) 24.513,9.82 v5(24.775,9.557) ; v5(26.603,8.725) v2(27.01,8.725)
  Mid Layer 2 w0.2: v5(24.775,9.557) 25.608,8.725 v5(26.603,8.725)
SIM.CLK: M1.18 U16.8 | length 5.1
  Top Layer w0.15: v2(24.785,7.285) 24.65,7.15 24.65,5.997 24.922,5.725 U16.8@25.175,5.725
  Mid Layer 1 w0.15: v5(24.013,9.628) v2(24.013,10.075) ; v2(24.785,7.285) v5@24.785,7.754
  Mid Layer 2 w0.15: v5(24.013,9.628) 24.013,9.136 24.268,8.881 24.268,8.685 24.784,8.169 v5(24.784,7.755)
SIM.IO: M1.17 U16.4 | length 5
  Top Layer w0.15: v2(25.597,7.557) 25.8,7.354 U16.4@25.8,7.15
  Mid Layer 1 w0.15: v2(23.513,10.075) v5(23.513,10.569) ; v5(25.296,7.858) v2(25.597,7.557)
  Mid Layer 2 w0.15: v5(23.513,10.569) 23.513,10.447 23.894,10.065 24.167,10.065 24.38,9.852 24.38,9.231 25.198,8.414 25.198,7.956 v5(25.296,7.858)
SIM.RST: M1.16 U16.12 | length 8.3
  Top Layer w0.15: v2(23.013,10.075) M1.16@23.017,10.075 ; v2(24.375,7.539) 24.375,5.675 25.1,4.95 26.703,4.95 26.91,5.157 26.91,5.16 26.965,5.215 26.965,5.231 27,5.266 U16.12@27,5.5
  Mid Layer 1 w0.15: v5(23.013,9.645) v2(23.013,10.075) ; v2(24.375,7.539) v5(24.375,7.95)
  Mid Layer 2 w0.15: v5(23.013,9.645) 23.078,9.645 23.945,8.777 23.945,8.38 v5(24.375,7.95)
SW0: L9.1 U25.J4 | length 4
  Bottom Layer w0.2: 14.2,34.175 14.38,33.995 U25.J4@14.515,33.995
  Bottom Layer w0.3: L9.1@11.55,35.9 11.693,35.758 12.625,34.825 13.739,34.825 14.025,34.539 14.025,34.35 14.275,34.1
SW1: L7.2 U11.3 | length 4.4
  Bottom Layer w0.3: U11.3@13.25,42.35 13.85,42.35 14.65,43.15 16.64,43.15 17.05,42.74 L7.2@17.1,42.74
SW2: L8.2 U11.5 | length 3.8
  Bottom Layer w0.3: U11.5@13.25,41.35 13.85,41.35 14.65,40.55 16.69,40.55 L8.2@16.715,40.575
SW3: L10.1 U25.J2 | length 3.2
  Bottom Layer w0.2: 14.2,32.975 14.38,33.155 U25.J2@14.515,33.155
  Bottom Layer w0.3: L10.1@12.125,31.825 12.625,32.325 13.739,32.325 14.025,32.611 14.025,32.8 14.275,33.05
SW_CTRL1: R60.2 U21.45 | length 1
  Top Layer w0.125: U21.45@27.75,36.775 R60.2@28.778,36.775
SWD1_CLK: R4.1 U6.L1 | length 1
  Bottom Layer w0.105: U6.L1@19.075,22.63 19.605,22.1 R4.1@19.605,21.84
SWD1_IO: R6.1 U6.H1 | length 2.6
  Bottom Layer w0.105: U6.H1@19.075,23.68 19.173,23.68 20.743,22.11 20.743,22.025 20.891,21.877 R6.1@20.891,21.84
SWD1_RESET: R16.1 U6.G3 | length 5.5
  Mid Layer 4 w0.125: v7(18.375,24.03) 17.971,24.03 17.818,23.877 17.818,23.463 18.361,22.92 19.132,22.92 19.318,23.105 20.233,23.105 v1(21.015,22.323)
  Bottom Layer w0.125: v1(21.015,22.323) 21.462,21.876 R16.1@21.462,21.84
SWDCLK: P8.4 P9.6 TP27.1 U12.4 | length 20.9
  Top Layer w0.15: P8.4@7.285,10.664 7.01,10.389 7.01,10.299 7.01,6.654 7.419,6.245 8.25,6.245 cw(c8.25,4.9) 9.201,5.851 9.527,5.525 12.525,5.525 TP27.1@13.5,6.5 13.628,6.5 15.038,7.91 v6(15.038,8.086) ; P8.4@7.285,10.665 7.59,10.97 P8.4@8.225,10.97
  Mid Layer 1 w0.15: v4(5.938,10.3) v2(7.009,10.3)
  Mid Layer 4 w0.15: v1(4.97,10.295) 4.975,10.3 v4(5.938,10.3)
  Bottom Layer w0.15: v6(15.038,8.086) 15.307,8.355 18.285,8.355 18.55,8.089 U12.4@18.55,7.8
SWDIO: P8.2 P9.5 TP29.1 U12.16 | length 22
  Top Layer w0.15: P8.2@8.225,12.24 7.59,12.24 6.565,11.215 v2(6.565,9.5) 6.565,6.71 7.305,5.97 8.25,5.97 cw(c8.25,4.9) 9.007,5.657 9.413,5.25 15.25,5.25 TP29.1@16.5,6.5 16.325,6.675 v6(16.325,7.835)
  Mid Layer 1 w0.15: v4(5.941,9.5) v2(6.565,9.5)
  Mid Layer 4 w0.15: v1(4.973,9.495) 4.978,9.5 v4(5.941,9.5)
  Bottom Layer w0.15: P9.5@4.15,9.5 4.968,9.5 v1(4.973,9.495) ; v6@16.3,7.835 16.56,7.575 U12.16@16.725,7.575
SXLDO: C61.2 U21.11 | length 1.3
  Top Layer w0.152: C61.2@22.495,39.89 22.504,39.882 22.504,39.54 22.926,39.118 22.941,39.103 22.941,38.784 U21.11@22.95,38.775
USB.D_N: C99.1 R31.1 U6.A11 | length 7.3
  Bottom Layer w0.083: R31.1@10.572,26.583 10.572,26.07 10.535,26.033 ccw(c10.858,25.71) 10.401,25.71 ccw(c10.781,25.71) 10.512,25.441 10.564,25.389 ccw(c10.714,25.539) 10.714,25.327 10.92,25.327 ccw(c10.92,26.357) 11.105,25.343 ccw(c10.92,26.357) 11.648,25.628 ccw(c11.58,25.697) 11.677,25.697 11.677,26.011 cw(c12.183,26.011) 11.825,26.369 11.892,26.436 cw(c12.334,25.994) 12.334,26.619 14.686,26.619 cw(c14.686,25.655) 15.368,26.337 U6.A11@15.575,26.13
USB.D_P: C100.1 R34.1 U6.A12 | length 7.2
  Bottom Layer w0.083: R34.1@10.02,26.583 10.02,26.07 10.057,26.033 cw(c9.734,25.71) 10.191,25.71 ccw(c10.781,25.71) 10.364,25.292 10.415,25.24 ccw(c10.714,25.539) 10.714,25.116 10.96,25.116 ccw(c10.96,26.261) 11.128,25.129 ccw(c10.96,26.261) 11.769,25.452 11.797,25.48 ccw(c11.58,25.697) 11.887,25.697 11.887,26.011 cw(c12.183,26.011) 11.974,26.22 12.041,26.288 cw(c12.334,25.994) 12.334,26.409 14.686,26.409 cw(c14.686,25.783) 15.129,26.226 U6.A12@15.225,26.13
VBAT: C51.2 J3.3 TP4.1 U11.19 | length 19.7
  Top Layer w0.5: TP4.1@7,49 7.263,48.737 7.119,48.594 7.43,48.594 v6(8.231,47.793)
  Mid Layer 2 w0.5: v4(3.42,38.892) 3.42,41.509 2.796,42.133 2.796,45.548 5.374,48.125 7.898,48.125 v6(8.231,47.793)
  Mid Layer 4 w0.5: v4(3.42,38.892) v1(4.01,38.892) v1(4.457,38.892)
  Bottom Layer w0.5: v1(4.01,38.892) v1(4.457,38.892) 5.722,38.892 6.405,39.575 C51.2@6.405,39.7 ; v6(8.231,47.793) 8.238,47.8 J3.3@8.5,47.8
VBAT_nRF70: C64.2 C67.1 C68.2 C73.2 P9.2 TP13.1 U2.A1 U21.13 U21.20 U21.25 U21.31 | length 63.7
  Top Layer w0.14: C73.2@20.325,34.88 20.375,34.88 20.67,35.175 U21.20@21.75,35.175
  Top Layer w0.152: 22.433,32.775 U21.25@22.55,32.775
  Top Layer w0.23: C68.2@20.603,38.75 20.603,38.517 20.63,38.49 20.863,38.49 21.378,37.975 U21.13@21.75,37.975
  Top Layer w0.254: v9(12.172,29.278) TP13.1@12.5,28.95 ; C73.2@20.145,34.7 19.96,34.515 19.96,32.99 20.175,32.775 v2(21.75,32.775) 22.433,32.775 ; U21.31@24.95,32.775 24.95,31.772 24.95,31.031 C67.1@24.959,31.022
  Top Layer w0.4: C68.2@20.289,38.856 C68.2@20.37,38.775
  Mid Layer 1 w0.25: v2(20.363,38.815) v5(20.686,38.492) ; v2(21.75,32.775) v5(21.75,33.232) ; v2(24.934,31.772) v5(24.934,32.229)
  Mid Layer 1 w0.254: v4(11.333,30.123) 11.333,30.117 v9(12.172,29.278)
  Mid Layer 2 w0.25: v5(20.686,38.492) 21.038,38.14 21.038,33.944 v5(21.75,33.232) 22.207,32.775 24.388,32.775 v5(24.934,32.229)
  Mid Layer 2 w0.5: v4(11.14,31.875) 11.719,31.875 14.619,28.975 18.945,28.975 19.725,29.755 19.725,33.475
  Mid Layer 3 w0.254: 9.298,30.075 9.346,30.123 v4(11.333,30.123)
  Mid Layer 3 w0.5: 4.693,7.1 4.2,7.593 4.2,21.025 9.298,26.123 9.298,30.075 9.298,30.775
  other v1: 3.325,7.1 3.75,7.1 4.175,7.1 4.6,7.1 8.625,31.675 9.05,31.675 8.625,32.1 9.05,32.1
  other v3: 5,7.1 5.425,7.1 5.85,7.1 6.275,7.1 9.462,31.67 9.912,31.67 9.462,32.095 9.912,32.095
  other v4: 10.425,31.875
  other v5: 19.5,33.5 19.925,33.5 19.5,33.95 19.925,33.95
  other v9: 19.5,32.575 19.925,32.575 19.5,33.025 19.925,33.025
VBUS: C44.2 C46.2 FB2.2 U11.21 | length 4.1
  Mid Layer 3 w0.5: v3@5.325,38.675 5.325,41.875 5.95,42.5
  other v1: 5.35,38.15 5.775,38.15 6.2,38.15 6.625,38.15 5.989,42.102 6.414,42.102 6.839,42.102 5.989,42.552 6.414,42.552
  other v3: 5.35,38.55 5.775,38.55 6.2,38.55 6.625,38.55 6.839,42.45 5.989,42.875 6.414,42.875 6.839,42.875
VBUS_CONN: C11.2 C14.2 C43.2 FB2.1 J6.A4 J6.A9 TP12.1 U8.1 | length 8.3
  Top Layer w0.4: v6(8.2,33.675) 8.2,33.25 TP12.1@9.5,31.95
  Bottom Layer w0.4: 7.863,33.65 7.888,33.675 v6(8.2,33.675)
  Bottom Layer w0.5: FB2.1@6.425,37.525 FB2.1@6.475,37.525 6.975,37.525 7.863,36.637 7.863,33.65 7.863,32.963 v1(7.75,32.85) v1@7.7,32.8
  other v1: 7.958,28.571 8.383,28.571 8.383,28.996 8.808,28.996 6.475,32.85 6.9,32.85 7.325,32.85
  other v3: 7.533,28.146 7.958,28.146 7.533,28.571 7.533,28.996 7.958,28.996 6.475,32.45 6.9,32.45 7.325,32.45 7.75,32.45
VBUSOUT: C50.2 R10.1 U11.22 | length 21
  Mid Layer 3 w0.25: v3@5.844,43.423 5.456,43.423 4.825,42.793 4.825,38.904 4.825,38.15 10.375,32.6 11.55,32.6 12.425,31.725 v3(12.425,30.975)
  Mid Layer 4 w0.25: v3(5.946,43.423) 6.43,43.423 v1(6.506,43.5) ; v1(12.25,30.232) 12.402,30.232 12.425,30.255 v3(12.425,30.975)
  Bottom Layer w0.25: v1(12.25,30.232) 12.385,30.097 12.385,30.08 R10.1@12.425,30.12
  Bottom Layer w0.3: v1(6.506,43.5) 6.617,43.5 7.174,42.943 7.767,42.35 U11.22@8.35,42.35
VCOM0.RXD: M1.57 U6.K3 | length 6.4
  Mid Layer 1 w0.125: v4(16.976,19.764) 16.976,21.288 v2(17.013,21.325)
  Mid Layer 4 w0.125: v4@17.056,19.759 18.045,19.759 18.448,20.162 18.512,20.162 v1(18.915,20.565)
  Bottom Layer w0.105: U6.K3@18.375,22.98 18.615,22.74 18.615,22.039 18.836,21.819
  Bottom Layer w0.125: 18.836,21.819 18.836,20.644 v1(18.915,20.565)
